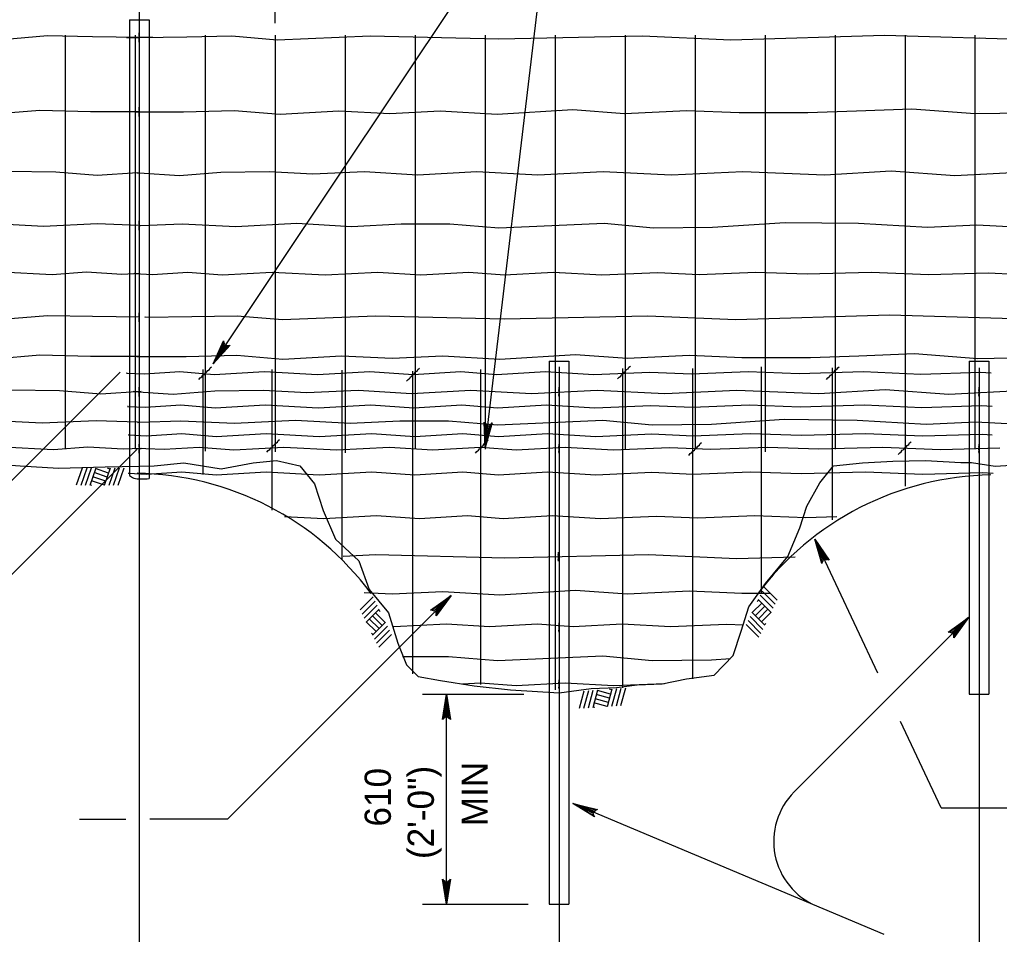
# Model space of a CAD drawing. Extents: x 13 to 918, y -903 to 879.
# Drawn here: x 358.1 to 474.8, y -225.3 to -116.4 of the extents above; entities that cross this region are included whole.
import ezdxf

# ---------------------------------------------------------------- set-up
doc = ezdxf.new("R2010")
doc.units = 0
for name, color, linetype in [('1', 7, 'Continuous'), ('2', 7, 'Continuous'), ('3', 7, 'Continuous')]:
    doc.layers.add(name, color=color, linetype=linetype)

msp = doc.modelspace()

# ---------------------------------------------------------------- linework, layer by layer
at = {"layer": '1'}
for p, q in [((365.5315, -169.833), (364.82925, -171.858)), ((366.073, -169.833), (365.3585, -171.8955)), ((366.61475, -169.833), (365.90025, -171.8955)), ((367.1565, -169.833), (366.44175, -171.8955)), ((368.6815, -170.41625), (367.13975, -169.883)), ((368.86675, -169.833), (368.15225, -171.8955)), ((368.848, -169.933), (368.56275, -169.833)), ((369.4085, -169.833), (368.694, -171.8955)), ((369.948, -169.833), (369.2355, -171.8955)), ((370.49175, -169.833), (369.77725, -171.8955)), ((368.17925, -171.86625), (366.6355, -171.333)), ((368.348, -171.383), (366.80425, -170.8495)), ((368.51475, -170.8995), (366.973, -170.36425)), ((366.694, -171.8955), (366.469, -171.81625)), ((446.75425, -183.99325), (448.294, -185.537)), ((400.1815, -185.16425), (398.64175, -186.708)), ((446.044, -185.45375), (447.5855, -186.9995)), ((446.2815, -184.96425), (447.823, -186.51425)), ((446.51675, -184.483), (448.0585, -186.0245)), ((400.419, -185.65375), (398.87725, -187.1955)), ((400.65425, -186.135), (399.11275, -187.685)), ((400.89175, -186.6245), (399.35025, -188.1705)), ((446.4855, -185.8745), (445.3315, -187.02675)), ((446.848, -186.235), (445.69175, -187.38925)), ((446.12525, -185.51425), (445.9105, -185.7245)), ((447.2085, -186.5975), (446.05225, -187.75175)), ((399.72725, -187.76825), (400.8835, -188.9225)), ((400.08775, -187.40575), (401.244, -188.56)), ((400.45025, -187.0455), (401.60425, -188.1975)), ((400.8105, -186.685), (401.02525, -186.8955)), ((445.0565, -187.47875), (446.596, -189.0225)), ((445.294, -186.99125), (446.8335, -188.537)), ((447.569, -186.962), (446.41275, -188.11825)), ((399.36675, -188.133), (400.523, -189.28925)), ((401.64175, -188.162), (400.10225, -189.708)), ((401.87925, -188.6495), (400.33975, -190.19325)), ((444.5815, -188.4495), (446.094, -189.96825)), ((444.819, -187.96425), (446.3585, -189.51)), ((446.946, -188.31), (446.77725, -188.47675)), ((399.98975, -189.48075), (400.1585, -189.6475)), ((402.11675, -189.135), (400.57725, -190.68075)), ((402.35425, -189.6205), (400.84175, -191.13925)), ((425.271, -196.36625), (424.71275, -198.435)), ((425.8105, -196.32875), (425.24175, -198.435)), ((426.35025, -196.29125), (425.7835, -198.3975)), ((426.89175, -196.25375), (426.323, -198.36)), ((428.323, -197.2225), (426.746, -196.7975)), ((428.45425, -196.72875), (426.87925, -196.30375)), ((428.598, -196.135), (428.02925, -198.24325)), ((428.5855, -196.235), (428.296, -196.15575)), ((429.13975, -196.0955), (428.569, -198.20575)), ((429.67525, -196.058), (429.1105, -198.16625)), ((430.219, -196.0205), (429.65025, -198.12675)), ((426.57525, -198.34325), (426.346, -198.28075)), ((428.05425, -198.21), (426.47525, -197.787)), ((428.18975, -197.71625), (426.6105, -197.29125))]:
    msp.add_line(p, q, dxfattribs=at)
at = {"layer": '2'}
for p, q in [((388.521, -116.82675), (388.521, -103.15175)), ((372.32525, -112.8975), (372.32525, -240.62675)), ((371.15025, -116.4475), (373.50025, -116.4475)), ((371.15025, -116.4475), (371.15025, -170.68925)), ((373.50025, -116.4475), (373.50025, -171.0725)), ((363.523, -118.262), (363.523, -167.562)), ((371.8565, -118.262), (371.8565, -167.562)), ((372.32525, -118.54125), (372.32525, -118.54125)), ((380.18975, -118.262), (380.18975, -167.79325)), ((388.521, -118.262), (388.521, -167.88925)), ((396.85425, -118.262), (396.85425, -168.00375)), ((405.1855, -118.262), (405.1855, -167.562)), ((413.519, -118.262), (413.519, -167.562)), ((421.85225, -118.262), (421.85225, -167.562)), ((422.32525, -118.54125), (422.32525, -118.54125)), ((430.1835, -118.262), (430.1835, -167.562)), ((438.51675, -118.262), (438.51675, -167.562)), ((446.848, -118.262), (446.848, -167.8705)), ((455.1815, -118.262), (455.1815, -167.562)), ((463.51475, -118.262), (463.51475, -171.95575)), ((471.846, -118.262), (471.846, -167.562)), ((472.32525, -118.54125), (472.32525, -118.54125)), ((372.32525, -127.3955), (372.32525, -127.3955)), ((422.32525, -127.3955), (422.32525, -127.3955)), ((472.32525, -127.3955), (472.32525, -127.3955)), ((372.32525, -134.687), (372.32525, -134.687)), ((422.32525, -134.687), (422.32525, -134.687)), ((472.32525, -134.687), (472.32525, -134.687)), ((372.32525, -140.937), (372.32525, -140.937)), ((422.32525, -140.937), (422.32525, -140.937)), ((472.32525, -140.937), (472.32525, -140.937)), ((372.32525, -146.66625), (372.32525, -146.66625)), ((422.32525, -146.66625), (422.32525, -146.66625)), ((472.32525, -146.66625), (472.32525, -146.66625)), ((372.32525, -151.8745), (372.32525, -151.8745)), ((422.32525, -151.8745), (422.32525, -151.8745)), ((472.32525, -151.8745), (472.32525, -151.8745)), ((372.32525, -156.562), (372.32525, -156.562)), ((421.15025, -157.083), (423.50025, -157.083)), ((421.15025, -157.083), (421.15025, -197.2955)), ((421.8565, -157.083), (421.8565, -196.2205)), ((423.50025, -157.083), (423.50025, -196.91)), ((471.15025, -157.083), (473.50025, -157.083)), ((471.15025, -157.083), (471.15025, -196.758)), ((473.50025, -157.083), (473.50025, -196.758)), ((379.90225, -158.06825), (379.90225, -170.5745)), ((388.1355, -158.06825), (388.1355, -174.812)), ((396.471, -158.16425), (396.471, -180.7225)), ((404.87925, -158.26), (404.87925, -194.3205)), ((412.9815, -158.06825), (412.9815, -195.60575)), ((422.32525, -157.78075), (422.32525, -239.858)), ((429.87725, -157.9725), (429.87725, -195.98925)), ((438.18975, -157.9725), (438.18975, -194.8975)), ((446.369, -157.78075), (446.369, -184.712)), ((454.85425, -157.87675), (454.85425, -175.983)), ((472.32525, -157.87675), (472.32525, -240.8745)), ((372.32525, -160.72875), (372.32525, -160.72875)), ((422.32525, -160.72875), (422.32525, -160.72875)), ((472.32525, -160.72875), (472.32525, -160.72875)), ((372.32525, -164.3745), (372.32525, -164.3745)), ((422.32525, -164.3745), (422.32525, -164.3745)), ((472.32525, -164.3745), (472.32525, -164.3745)), ((372.32525, -167.4995), (372.32525, -167.4995)), ((422.32525, -167.4995), (422.32525, -167.4995)), ((472.32525, -167.4995), (472.32525, -167.4995)), ((422.32525, -169.00175), (422.32525, -169.00175)), ((372.32525, -169.583), (372.32525, -169.583)), ((372.32525, -169.583), (372.32525, -169.583)), ((372.32525, -169.583), (372.32525, -169.583)), ((372.32525, -169.583), (372.32525, -169.583)), ((422.32525, -169.583), (422.32525, -169.583)), ((422.32525, -169.583), (422.32525, -169.583)), ((422.32525, -169.583), (422.32525, -169.583)), ((422.32525, -169.583), (422.32525, -169.583)), ((422.32525, -169.583), (422.32525, -169.583)), ((472.32525, -169.583), (472.32525, -169.583)), ((472.32525, -169.583), (472.32525, -169.583)), ((472.32525, -169.583), (472.32525, -169.583)), ((472.32525, -169.583), (472.32525, -169.583)), ((472.32525, -169.583), (472.32525, -169.583)), ((472.32525, -169.583), (472.32525, -169.583)), ((422.32525, -174.73075), (422.32525, -174.73075)), ((422.32525, -179.93925), (422.32525, -179.93925)), ((422.32525, -188.79325), (422.32525, -188.79325)), ((422.32525, -192.43925), (422.32525, -192.43925)), ((422.32525, -194.583), (422.32525, -194.583)), ((422.32525, -195.56425), (422.32525, -195.56425)), ((406.05225, -196.758), (418.1355, -196.758)), ((408.90425, -221.758), (408.90425, -196.758)), ((423.50025, -196.91), (423.50025, -221.758)), ((471.15025, -196.758), (473.50025, -196.758)), ((421.15025, -197.2955), (421.15025, -221.758)), ((467.82525, -210.287), (479.844, -210.287)), ((365.22175, -211.62475), (370.72875, -211.62475)), ((373.58425, -211.5725), (382.86675, -211.5725)), ((406.05225, -221.758), (418.6355, -221.758)), ((421.15025, -221.758), (423.50025, -221.758))]:
    msp.add_line(p, q, dxfattribs=at)
for points in [[(373.9585, -118.54125), (372.396, -118.54125), (366.77925, -118.45375), (361.38975, -118.358), (355.998, -118.81825), (344.9315, -118.358), (342.594, -118.41425)], [(370.80425, -118.54125), (372.36675, -118.54125), (377.9835, -118.45375), (383.373, -118.358), (388.76475, -118.81825), (399.8315, -118.358), (415.1585, -118.7225), (432.269, -118.358), (442.7605, -118.81825), (461.0605, -118.262), (479.83775, -118.81825), (499.15425, -118.16625), (499.57525, -118.185)], [(372.32525, -119.08925), (372.3085, -118.8975), (372.33975, -118.787), (372.31275, -118.63925), (372.346, -118.4975), (372.3085, -118.33925), (372.3355, -118.18075), (372.32525, -117.99325)], [(371.821, -127.3955), (371.821, -127.3955), (377.61675, -127.3955), (383.63975, -127.2245), (389.12525, -127.685), (396.1085, -127.2995), (402.15025, -127.58925), (408.173, -127.2995), (414.96275, -127.685), (423.97925, -127.12875), (430.11675, -127.58925), (437.53975, -127.2245), (443.773, -127.49325), (451.946, -127.49325), (457.719, -127.2995), (464.31675, -127.033), (471.87525, -127.608), (477.72525, -127.512), (485.26475, -127.33925), (494.08775, -127.05175), (499.57525, -127.39125)], [(372.32525, -127.94325), (372.3085, -127.75175), (372.33975, -127.64125), (372.31275, -127.49325), (372.346, -127.35175), (372.3085, -127.19325), (372.3355, -127.035), (372.32525, -126.8475)], [(372.32525, -127.3955), (372.32525, -127.3955), (366.52925, -127.3955), (360.5065, -127.2245), (355.021, -127.685), (348.03775, -127.2995), (342.594, -127.562)], [(372.32525, -134.687), (372.12925, -134.67675), (367.33775, -134.98075), (362.4085, -134.5975), (356.65225, -134.50175), (351.45425, -134.78925), (345.31675, -134.50175), (342.594, -134.66825)], [(372.12925, -134.687), (372.32525, -134.67675), (377.11675, -134.98075), (382.046, -134.5975), (387.80225, -134.50175), (393.00025, -134.78925), (399.13775, -134.50175), (405.46675, -134.885), (412.52725, -134.50175), (419.77725, -134.885), (427.5835, -134.50175), (435.6605, -134.885), (444.21475, -134.50175), (453.97925, -134.885), (461.86275, -134.4245), (469.4585, -134.962), (478.569, -134.50175), (488.9855, -134.962), (499.2085, -134.50175), (499.57525, -134.52675)], [(372.32525, -140.937), (372.2835, -140.92675), (367.33775, -140.7495), (360.9315, -141.037), (353.6815, -140.6725), (347.17725, -141.037), (342.594, -140.81625)], [(372.32525, -141.485), (372.3085, -141.29325), (372.33975, -141.183), (372.31275, -141.035), (372.346, -140.89325), (372.3085, -140.735), (372.3355, -140.57675), (372.32525, -140.38925)], [(372.43775, -140.937), (372.47925, -140.92675), (377.42525, -140.7495), (383.8315, -141.037), (391.0815, -140.6725), (397.5855, -141.037), (403.5315, -140.7495), (409.30425, -140.7495), (415.15425, -141.22875), (421.46675, -140.94125), (427.70025, -140.6725), (433.55025, -141.22875), (440.6085, -141.133), (449.2605, -140.57675), (457.98775, -140.6725), (466.17925, -141.133), (472.048, -140.86425), (477.43775, -141.15175), (483.65225, -141.05575), (491.00025, -140.787), (497.78975, -140.4995), (499.57525, -140.60575)], [(372.32525, -146.66625), (372.396, -146.65575), (370.25025, -146.7495), (366.05025, -146.48075), (361.946, -146.8245), (355.97925, -146.48075), (349.669, -146.8245), (343.41475, -146.48075), (342.594, -146.537)], [(371.821, -146.66625), (371.75025, -146.65575), (373.896, -146.7495), (378.096, -146.48075), (382.20025, -146.8245), (388.16675, -146.48075), (394.47725, -146.8245), (400.7315, -146.48075), (405.871, -146.8245), (411.569, -146.48075), (415.82725, -146.8245), (421.6585, -146.48075), (427.41275, -146.8245), (434.069, -146.537), (439.01675, -146.7495), (445.769, -146.48075), (451.869, -146.69125), (459.50225, -146.48075), (466.35025, -146.76825), (473.42925, -146.558), (480.0085, -146.90175)], [(372.32525, -152.4225), (372.3085, -152.23075), (372.33975, -152.1205), (372.31275, -151.9725), (372.346, -151.83075), (372.3085, -151.6725), (372.3355, -151.51425), (372.32525, -151.32675)], [(373.05225, -151.833), (372.97925, -151.86425), (378.596, -151.77675), (383.9855, -151.68075), (389.37725, -152.14125), (400.444, -151.68075), (415.771, -152.0455), (432.8815, -151.68075), (443.373, -152.14125), (461.673, -151.585), (480.45025, -152.14125), (499.57525, -151.4975)], [(372.323, -151.833), (372.396, -151.86425), (366.77925, -151.77675), (361.38975, -151.68075), (355.998, -152.14125), (344.9315, -151.68075), (342.594, -151.737)], [(372.15025, -156.5725), (372.0585, -156.55175), (377.92525, -156.55175), (383.948, -156.38075), (389.4335, -156.84125), (396.41675, -156.45575), (402.4585, -156.7455), (408.4815, -156.45575), (415.271, -156.84125), (424.28775, -156.285), (430.42525, -156.7455), (437.848, -156.38075), (444.0815, -156.6495), (452.25425, -156.6495), (458.02725, -156.45575), (464.62525, -156.18925), (472.1835, -156.76425), (478.0335, -156.66825), (485.573, -156.4955), (494.396, -156.208), (499.57525, -156.52875)], [(372.30425, -156.5725), (372.396, -156.55175), (366.52925, -156.55175), (360.5065, -156.38075), (355.021, -156.84125), (348.03775, -156.45575), (342.594, -156.71825)], [(370.8815, -158.5205), (370.8105, -158.51), (372.9565, -158.60375), (377.1565, -158.335), (381.2605, -158.67875), (387.22725, -158.335), (393.53775, -158.67875), (399.79175, -158.335), (404.9315, -158.67875), (410.62925, -158.335), (414.88775, -158.67875), (420.719, -158.335), (426.473, -158.67875), (433.12925, -158.39125), (438.07725, -158.60375), (444.82925, -158.335), (450.92925, -158.5455), (458.56275, -158.335), (465.4105, -158.6225), (472.48975, -158.412), (473.77725, -158.47875)], [(379.42525, -159.285), (379.594, -159.07875), (379.78975, -158.95175), (379.894, -158.7745), (380.08975, -158.6705), (380.18775, -158.49125), (380.3565, -158.387), (380.4835, -158.19125), (380.67925, -158.087), (380.77725, -157.89125), (380.946, -157.76425)], [(404.169, -159.458), (404.33775, -159.25175), (404.5335, -159.1245), (404.63775, -158.9475), (404.8335, -158.84325), (404.9315, -158.66425), (405.10025, -158.56), (405.22725, -158.36425), (405.423, -158.26), (405.521, -158.06425), (405.68975, -157.937)], [(429.296, -159.18925), (429.46475, -158.983), (429.6605, -158.85575), (429.76475, -158.67875), (429.9605, -158.5745), (430.0585, -158.3955), (430.22725, -158.29125), (430.35425, -158.0955), (430.55025, -157.99125), (430.648, -157.7955), (430.81675, -157.66825)], [(454.1565, -159.26625), (454.32525, -159.06), (454.521, -158.933), (454.62525, -158.75575), (454.821, -158.65175), (454.919, -158.4725), (455.08775, -158.36825), (455.21475, -158.1725), (455.4105, -158.06825), (455.5085, -157.8725), (455.67725, -157.7455)], [(372.32525, -160.72875), (372.55025, -160.71825), (367.7585, -161.0225), (362.82925, -160.63925), (357.073, -160.54325), (351.87525, -160.83075), (345.73775, -160.54325), (342.594, -160.735)], [(371.821, -160.72875), (371.596, -160.71825), (376.38775, -161.0225), (381.31675, -160.63925), (387.073, -160.54325), (392.271, -160.83075), (398.4085, -160.54325), (404.73775, -160.92675), (411.798, -160.54325), (419.048, -160.92675), (426.85425, -160.54325), (434.9315, -160.92675), (443.4855, -160.54325), (453.25025, -160.92675), (461.1335, -160.46625), (468.72925, -161.00375), (477.83975, -160.54325), (488.2565, -161.00375), (498.47925, -160.54325), (499.57525, -160.61625)], [(372.32525, -161.27675), (372.3085, -161.085), (372.33975, -160.9745), (372.31275, -160.82675), (372.346, -160.685), (372.3085, -160.52675), (372.3355, -160.36825), (372.32525, -160.18075)], [(422.32525, -161.27675), (422.3085, -161.085), (422.33975, -160.9745), (422.31275, -160.82675), (422.346, -160.685), (422.3085, -160.52675), (422.3355, -160.36825), (422.32525, -160.18075)], [(472.32525, -161.27675), (472.3085, -161.085), (472.33975, -160.9745), (472.31275, -160.82675), (472.346, -160.685), (472.3085, -160.52675), (472.3355, -160.36825), (472.32525, -160.18075)], [(370.996, -162.49125), (370.92525, -162.48075), (373.071, -162.5745), (377.271, -162.30575), (381.37525, -162.6495), (387.34175, -162.30575), (393.65225, -162.6495), (399.9065, -162.30575), (405.046, -162.6495), (410.744, -162.30575), (415.00225, -162.6495), (420.8335, -162.30575), (426.58775, -162.6495), (433.244, -162.362), (438.19175, -162.5745), (444.944, -162.30575), (451.044, -162.51625), (458.67725, -162.30575), (465.52525, -162.59325), (472.60425, -162.383), (473.89175, -162.4495)], [(372.32525, -164.3745), (372.12925, -164.36425), (367.1835, -164.187), (360.77725, -164.4745), (353.52725, -164.11), (347.023, -164.4745), (342.594, -164.262)], [(372.12925, -164.3745), (372.32525, -164.36425), (377.271, -164.187), (383.67725, -164.4745), (390.92725, -164.11), (397.4315, -164.4745), (403.37725, -164.187), (409.15025, -164.187), (415.00025, -164.66625), (421.31275, -164.37875), (427.546, -164.11), (433.396, -164.66625), (440.45425, -164.5705), (449.1065, -164.01425), (457.8335, -164.11), (466.02525, -164.5705), (471.894, -164.30175), (477.2835, -164.58925), (483.498, -164.49325), (490.846, -164.2245), (497.6355, -163.937), (499.57525, -164.05175)], [(371.1105, -165.887), (371.03975, -165.87675), (373.1855, -165.9705), (377.3855, -165.70175), (381.48975, -166.0455), (387.4565, -165.70175), (393.76675, -166.0455), (400.021, -165.70175), (405.1605, -166.0455), (410.8585, -165.70175), (415.11675, -166.0455), (420.948, -165.70175), (426.70225, -166.0455), (433.3585, -165.758), (438.3065, -165.9705), (445.0585, -165.70175), (451.1585, -165.912), (458.79175, -165.70175), (465.63975, -165.98925), (472.719, -165.77875), (473.90025, -165.84125)], [(387.519, -167.937), (387.68775, -167.73075), (387.8835, -167.60375), (387.98775, -167.42675), (388.1835, -167.3225), (388.2815, -167.14325), (388.45025, -167.03925), (388.57725, -166.84325), (388.773, -166.73925), (388.871, -166.54325), (389.03975, -166.41625)], [(412.3605, -168.033), (412.52925, -167.82675), (412.72525, -167.6995), (412.82925, -167.5225), (413.02525, -167.41825), (413.123, -167.23925), (413.29175, -167.135), (413.419, -166.93925), (413.61475, -166.835), (413.71275, -166.63925), (413.8815, -166.512)], [(437.77525, -168.30175), (437.944, -168.0955), (438.13975, -167.96825), (438.244, -167.79125), (438.43975, -167.687), (438.53775, -167.508), (438.7065, -167.40375), (438.8335, -167.208), (439.02925, -167.10375), (439.12725, -166.908), (439.296, -166.78075)], [(462.7105, -168.20575), (462.87925, -167.9995), (463.07525, -167.8725), (463.17925, -167.6955), (463.37525, -167.59125), (463.473, -167.412), (463.64175, -167.308), (463.769, -167.112), (463.96475, -167.008), (464.06275, -166.812), (464.2315, -166.685)], [(372.32525, -167.4995), (372.55025, -167.48925), (370.40425, -167.583), (366.20425, -167.31425), (362.10025, -167.658), (356.1335, -167.31425), (349.823, -167.658), (343.569, -167.31425), (342.594, -167.38075)], [(372.32525, -168.0475), (372.3085, -167.85575), (372.33975, -167.7455), (372.31275, -167.5975), (372.346, -167.45575), (372.3085, -167.2975), (372.3355, -167.13925), (372.32525, -166.95175)], [(372.496, -167.46625), (373.1335, -167.48925), (375.27925, -167.583), (379.47925, -167.31425), (383.5835, -167.658), (389.55025, -167.31425), (395.8605, -167.658), (402.11475, -167.31425), (407.25425, -167.658), (412.95225, -167.31425), (417.2105, -167.658), (423.04175, -167.31425), (428.796, -167.658), (435.45225, -167.3705), (440.40025, -167.583), (447.15225, -167.31425), (453.25225, -167.5245), (460.8855, -167.31425), (467.7335, -167.60175), (474.81275, -167.39125)], [(422.32525, -168.0475), (422.3085, -167.85575), (422.33975, -167.7455), (422.31275, -167.5975), (422.346, -167.45575), (422.3085, -167.2975), (422.3355, -167.13925), (422.32525, -166.95175)], [(472.32525, -168.0475), (472.3085, -167.85575), (472.33975, -167.7455), (472.31275, -167.5975), (472.346, -167.45575), (472.3085, -167.2975), (472.3355, -167.13925), (472.32525, -166.95175)], [(374.1085, -169.537), (377.63975, -169.212), (382.069, -169.9225), (385.88775, -169.212), (388.68775, -168.90575), (391.45225, -169.54325), (393.21475, -171.687), (394.25025, -174.88925), (395.68975, -178.285), (398.48975, -180.8745), (399.71675, -184.2705), (402.00025, -187.0705), (403.1315, -190.67675), (404.16675, -193.2475), (405.52925, -194.64325), (408.196, -195.108), (412.20425, -195.74125), (416.53975, -196.23925), (422.3315, -196.56625), (426.15025, -196.0475), (429.14175, -195.933), (431.61675, -195.6245), (434.6085, -195.52875), (437.50425, -194.8975), (440.80425, -194.49325), (443.06675, -192.11625), (443.98775, -189.237), (444.92725, -186.34125), (446.8855, -183.56), (449.571, -180.358), (451.0085, -176.94325), (451.8335, -174.3725), (453.38775, -171.59125), (454.998, -169.54125), (458.45225, -169.212), (462.0585, -169.00175), (465.971, -168.90575), (470.17725, -169.1725)], [(470.17725, -169.1725), (471.41675, -169.15575), (474.25025, -169.583), (483.15425, -169.0205), (491.9605, -169.583), (495.31675, -169.44325), (498.1355, -169.3475), (506.10225, -169.10575)], [(335.96275, -169.385), (342.72525, -169.385), (348.03975, -169.308), (353.123, -169.212), (358.16675, -169.558), (362.7335, -169.8455), (368.2565, -169.65375), (372.32525, -169.583), (374.1085, -169.537)], [(371.1105, -170.45175), (371.03975, -170.44125), (373.1855, -170.535), (377.3855, -170.26625), (381.48975, -170.61), (387.4565, -170.26625), (393.76675, -170.61), (400.021, -170.26625), (405.1605, -170.61), (410.8585, -170.26625), (415.11675, -170.61), (420.948, -170.26625), (426.70225, -170.61), (433.3585, -170.3225), (438.3065, -170.535), (445.0585, -170.26625), (451.1585, -170.47675), (458.79175, -170.26625), (465.63975, -170.55375), (472.719, -170.34325), (474.019, -170.412)], [(389.62725, -175.58075), (394.323, -175.82875), (400.57725, -175.485), (405.71675, -175.82875), (411.41475, -175.485), (415.673, -175.82875), (421.50425, -175.485), (427.2585, -175.82875), (433.91475, -175.54125), (438.86275, -175.75375), (445.61475, -175.485), (451.71475, -175.6955), (455.4065, -175.5975)], [(396.61275, -180.29125), (400.521, -180.12875), (415.848, -180.49325), (432.9585, -180.12875), (443.45025, -180.58925), (450.45425, -180.37875)], [(422.248, -180.91825), (422.2315, -180.72675), (422.26275, -180.61625), (422.2355, -180.46825), (422.269, -180.32675), (422.2315, -180.16825), (422.2585, -180.01), (422.248, -179.8225)], [(399.123, -184.6495), (402.4585, -184.81), (408.4815, -184.5205), (415.271, -184.90575), (424.28775, -184.3495), (430.42525, -184.81), (437.848, -184.4455), (444.0815, -184.71425), (447.47925, -184.71425)], [(402.494, -188.69125), (402.648, -188.6995), (408.90225, -188.35575), (414.04175, -188.6995), (419.73975, -188.35575), (423.998, -188.6995), (429.82925, -188.35575), (435.5835, -188.6995), (442.23975, -188.412), (444.298, -188.50175)], [(422.32525, -189.34125), (422.3085, -189.1495), (422.33975, -189.03925), (422.31275, -188.89125), (422.346, -188.7495), (422.3085, -188.59125), (422.3355, -188.433), (422.32525, -188.2455)], [(403.669, -192.25175), (409.15025, -192.25175), (415.00025, -192.73075), (421.31275, -192.44325), (427.546, -192.1745), (433.396, -192.73075), (440.45425, -192.635), (442.7355, -192.48925)], [(410.80225, -195.508), (412.95225, -195.37875), (417.2105, -195.7225), (423.04175, -195.37875), (428.796, -195.7225), (434.871, -195.46)], [(422.32525, -196.112), (422.3085, -195.9205), (422.33975, -195.81), (422.31275, -195.662), (422.346, -195.5205), (422.3085, -195.362), (422.3355, -195.20375), (422.32525, -195.01625)]]:
    msp.add_lwpolyline(points, dxfattribs=at)
for centre, start, end in [((371.51937, -205.79821), 36.5303083, 89.1195583), ((474.28733, -205.98988), 90.8804417, 143.4696917)]:
    msp.add_arc(centre, 35.36118, start, end, dxfattribs=at)
msp.add_spline([(371.15025, -170.68925), (371.67725, -171.01625), (372.54175, -171.112), (373.50025, -171.0725)], degree=3, dxfattribs=at)
at = {"layer": '3'}
for p, q in [((381.11475, -157.41625), (422.0315, -96.158)), ((413.5335, -167.35175), (422.0315, -96.158)), ((345.86675, -182.56825), (370.046, -158.38925)), ((354.8565, -184.78075), (372.07925, -167.558)), ((460.29025, -194.25175), (452.7835, -178.283)), ((382.86675, -211.5725), (409.46275, -184.97675)), ((450.31675, -208.37875), (471.09175, -187.60375)), ((467.82525, -210.287), (462.987, -199.993)), ((461.048, -225.3455), (423.96475, -209.7495))]:
    msp.add_line(p, q, dxfattribs=at)
for points in [[(382.98775, -155.25375), (382.7585, -155.22875), (381.11475, -157.41625), (382.98775, -155.25375), (383.171, -155.20175), (381.11475, -157.41625), (382.519, -155.0705), (382.40425, -154.8745), (381.11475, -157.41625), (382.37725, -154.6725), (382.40425, -154.8745)], [(414.223, -164.57675), (414.0065, -164.65575), (413.5335, -167.35175), (414.223, -164.57675), (414.36475, -164.4455), (413.5335, -167.35175), (413.723, -164.6245), (413.5335, -164.50175), (413.5335, -167.35175), (413.41675, -164.333), (413.5335, -164.50175)], [(453.669, -181.00375), (453.8085, -180.8205), (452.7835, -178.283), (453.669, -181.00375), (453.61675, -181.187), (452.7835, -178.283), (454.06675, -180.6955), (454.294, -180.6995), (452.7835, -178.283), (454.4815, -180.78075), (454.294, -180.6995)], [(407.20425, -186.73075), (407.423, -186.80175), (409.46275, -184.97675), (407.20425, -186.73075), (407.01275, -186.7455), (409.46275, -184.97675), (407.62725, -187.00175), (407.70025, -187.21625), (409.46275, -184.97675), (407.68775, -187.4225), (407.70025, -187.21625)], [(468.8335, -189.358), (469.05225, -189.42875), (471.09175, -187.60375), (468.8335, -189.358), (468.64175, -189.3725), (471.09175, -187.60375), (469.2565, -189.62875), (469.32925, -189.84325), (471.09175, -187.60375), (469.31675, -190.0495), (469.32925, -189.84325)], [(408.548, -199.5955), (408.75425, -199.48925), (408.90425, -196.758), (408.548, -199.5955), (408.423, -199.74125), (408.90425, -196.758), (409.03975, -199.487), (409.24175, -199.587), (408.90425, -196.758), (409.37925, -199.74125), (409.24175, -199.587)], [(426.44175, -211.17875), (426.42525, -210.9475), (423.96475, -209.7495), (426.44175, -211.17875), (426.52925, -211.3495), (423.96475, -209.7495), (426.5335, -210.683), (426.70425, -210.535), (423.96475, -209.7495), (426.898, -210.46825), (426.70425, -210.535)], [(409.2605, -218.9205), (409.05425, -219.02675), (408.90425, -221.758), (409.2605, -218.9205), (409.3855, -218.7745), (408.90425, -221.758), (408.769, -219.02875), (408.56675, -218.92875), (408.90425, -221.758), (408.42925, -218.7745), (408.56675, -218.92875)]]:
    msp.add_lwpolyline(points, dxfattribs=at)
msp.add_arc((456.20807, -214.27146), 8.3325, 135, 247.1944472, dxfattribs=at)

# ---------------------------------------------------------------- texts
for s, p in [('MIN', (413.83375, -212.46325)), ('610', (402.29175, -212.49825)), ('(2\'-0")', (407.41675, -216.37425))]:
    msp.add_text(s, height=3.124999, rotation=90, dxfattribs=at).set_placement(p)

doc.saveas('drawing.dxf')
